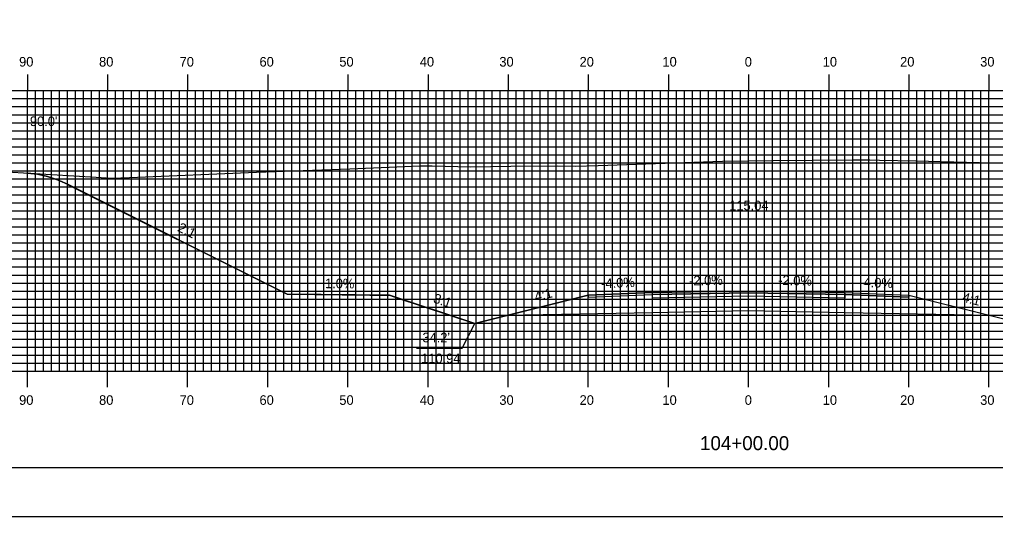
# Model space of a CAD drawing. Extents: x 1767694 to 1768037, y 442591 to 442811.
# Drawn here: x 1767768.5 to 1767890.3, y 442590.5 to 442652.5 of the extents above; entities that cross this region are included whole.
import ezdxf

# ---------------------------------------------------------------- set-up
doc = ezdxf.new("R2010")
doc.units = 0
for name, color, linetype in [('ANNOTATION', 7, 'Continuous'), ('BORDER', 7, 'Continuous'), ('D_Roadway_Centerline', 7, 'Continuous'), ('D_Roadway_Centerline_Text', 7, 'Continuous'), ('D_Roadway_Edge_Shoulder', 7, 'Continuous'), ('D_Roadway_Edge_TW', 7, 'Continuous'), ('D_Roadway_Pavement', 7, 'Continuous'), ('D_Roadway_SlopeLines', 7, 'Continuous'), ('D_Roadway_SubGrade', 7, 'Continuous'), ('D_Text_Standard', 7, 'Continuous'), ('H_V ANNOTATION', 7, 'Continuous'), ('MAJOR', 7, 'Continuous'), ('MINOR', 7, 'Continuous'), ('PLOT BOUNDARY', 7, 'Continuous'), ('S_Roadway_Centerline', 7, 'Continuous')]:
    doc.layers.add(name, color=color, linetype=linetype)

msp = doc.modelspace()

# ---------------------------------------------------------------- linework, layer by layer
at = {"layer": 'ANNOTATION'}
msp.add_lwpolyline([(1767818.02, 442611.54), (1767823.71, 442611.54), (1767825.28, 442614.6)], dxfattribs=at)
at = {"layer": 'BORDER'}
msp.add_lwpolyline([(1767709.85, 442596.67), (1768029.85, 442596.67), (1768029.85, 442806.67), (1767709.85, 442806.67)], close=True, dxfattribs=at)
at = {"layer": 'D_Roadway_Centerline'}
msp.add_lwpolyline([(1767769.45, 442633.39), (1767770.7, 442633.25), (1767771.95, 442632.96), (1767772.57, 442632.76), (1767773.2, 442632.54), (1767773.52, 442632.4), (1767774.45, 442631.99), (1767774.46, 442631.98), (1767801.88, 442618.27), (1767801.88, 442618.27), (1767812.18, 442618.17), (1767814.64, 442618.15), (1767815.56, 442617.84), (1767825.27, 442614.6), (1767825.28, 442614.6), (1767829.27, 442615.6), (1767833.59, 442616.68), (1767839.45, 442618.15), (1767839.45, 442618.15), (1767839.45, 442618.15), (1767847.45, 442618.47), (1767847.45, 442618.47), (1767849.41, 442618.51), (1767859.45, 442618.71), (1767859.46, 442618.71), (1767871.45, 442618.47), (1767871.45, 442618.47), (1767879.45, 442618.15), (1767879.45, 442618.15), (1767889.62, 442615.6), (1767893.62, 442614.6)], dxfattribs=at)
at = {"layer": 'D_Roadway_Edge_Shoulder'}
for points in [[(1767847.45, 442618.47), (1767839.45, 442618.15), (1767839.45, 442617.9), (1767847.45, 442618.22)], [(1767871.45, 442618.47), (1767879.45, 442618.15), (1767879.45, 442617.9), (1767871.45, 442618.22)]]:
    msp.add_lwpolyline(points, close=True, dxfattribs=at)
at = {"layer": 'D_Roadway_Edge_TW'}
msp.add_lwpolyline([(1767847.45, 442618.22), (1767847.45, 442618.47), (1767859.45, 442618.71), (1767871.45, 442618.47), (1767871.45, 442618.22), (1767859.45, 442618.46)], close=True, dxfattribs=at)
at = {"layer": 'D_Roadway_Pavement'}
msp.add_lwpolyline([(1767847.45, 442617.8), (1767847.45, 442618.22), (1767859.45, 442618.46), (1767871.45, 442618.22), (1767871.45, 442617.8), (1767859.45, 442618.04)], close=True, dxfattribs=at)
at = {"layer": 'D_Roadway_SlopeLines'}
for points in [[(1767814.64, 442618.15), (1767801.88, 442618.27), (1767774.45, 442631.99), (1767773.2, 442632.54), (1767771.95, 442632.96), (1767770.7, 442633.25), (1767769.45, 442633.39)], [(1767825.28, 442614.6), (1767814.64, 442618.15)], [(1767839.45, 442618.15), (1767825.28, 442614.6)], [(1767879.45, 442618.15), (1767893.62, 442614.6)]]:
    msp.add_lwpolyline(points, dxfattribs=at)
at = {"layer": 'D_Roadway_SubGrade'}
msp.add_lwpolyline([(1767847.45, 442615.97), (1767829.27, 442615.6), (1767839.45, 442618.15), (1767839.45, 442617.9), (1767847.45, 442618.22), (1767859.45, 442618.46), (1767871.45, 442618.22), (1767879.45, 442617.9), (1767879.45, 442618.15), (1767889.62, 442615.6), (1767871.45, 442615.97), (1767859.45, 442616.21)], close=True, dxfattribs=at)
at = {"layer": 'MAJOR'}
for p, q in [((1767769.45, 442645.67), (1767769.45, 442643.67)), ((1767779.45, 442645.67), (1767779.45, 442643.67)), ((1767789.45, 442645.67), (1767789.45, 442643.67)), ((1767799.45, 442645.67), (1767799.45, 442643.67)), ((1767809.45, 442645.67), (1767809.45, 442643.67)), ((1767819.45, 442645.67), (1767819.45, 442643.67)), ((1767829.45, 442645.67), (1767829.45, 442643.67)), ((1767839.45, 442645.67), (1767839.45, 442643.67)), ((1767849.45, 442645.67), (1767849.45, 442643.67)), ((1767859.45, 442645.67), (1767859.45, 442643.67)), ((1767869.45, 442645.67), (1767869.45, 442643.67)), ((1767879.45, 442645.67), (1767879.45, 442643.67)), ((1767889.45, 442645.67), (1767889.45, 442643.67)), ((1767719.45, 442643.67), (1767999.45, 442643.67)), ((1767719.45, 442643.67), (1767999.45, 442643.67)), ((1767769.45, 442608.67), (1767769.45, 442643.67)), ((1767779.45, 442608.67), (1767779.45, 442643.67)), ((1767789.45, 442608.67), (1767789.45, 442643.67)), ((1767799.45, 442608.67), (1767799.45, 442643.67)), ((1767809.45, 442608.67), (1767809.45, 442643.67)), ((1767819.45, 442608.67), (1767819.45, 442643.67)), ((1767829.45, 442608.67), (1767829.45, 442643.67)), ((1767839.45, 442608.67), (1767839.45, 442643.67)), ((1767849.45, 442608.67), (1767849.45, 442643.67)), ((1767859.45, 442608.67), (1767859.45, 442643.67)), ((1767869.45, 442608.67), (1767869.45, 442643.67)), ((1767879.45, 442608.67), (1767879.45, 442643.67)), ((1767889.45, 442608.67), (1767889.45, 442643.67)), ((1767719.45, 442638.67), (1767999.45, 442638.67)), ((1767719.45, 442633.67), (1767999.45, 442633.67)), ((1767719.45, 442628.67), (1767999.45, 442628.67)), ((1767719.45, 442623.67), (1767999.45, 442623.67)), ((1767719.45, 442618.67), (1767999.45, 442618.67)), ((1767719.45, 442613.67), (1767999.45, 442613.67)), ((1767719.45, 442608.67), (1767999.45, 442608.67)), ((1767719.45, 442608.67), (1767999.45, 442608.67)), ((1767769.45, 442606.66), (1767769.45, 442608.67)), ((1767779.45, 442606.66), (1767779.45, 442608.67)), ((1767789.45, 442606.66), (1767789.45, 442608.67)), ((1767799.45, 442606.66), (1767799.45, 442608.67)), ((1767809.45, 442606.66), (1767809.45, 442608.67)), ((1767819.45, 442606.66), (1767819.45, 442608.67)), ((1767829.45, 442606.66), (1767829.45, 442608.67)), ((1767839.45, 442606.66), (1767839.45, 442608.67)), ((1767849.45, 442606.66), (1767849.45, 442608.67)), ((1767859.45, 442606.66), (1767859.45, 442608.67)), ((1767869.45, 442606.66), (1767869.45, 442608.67)), ((1767879.45, 442606.66), (1767879.45, 442608.67)), ((1767889.45, 442606.66), (1767889.45, 442608.67))]:
    msp.add_line(p, q, dxfattribs=at)
at = {"layer": 'MINOR'}
for p, q in [((1767770.45, 442608.67), (1767770.45, 442643.67)), ((1767771.45, 442608.67), (1767771.45, 442643.67)), ((1767772.45, 442608.67), (1767772.45, 442643.67)), ((1767773.45, 442608.67), (1767773.45, 442643.67)), ((1767774.45, 442608.67), (1767774.45, 442643.67)), ((1767775.45, 442608.67), (1767775.45, 442643.67)), ((1767776.45, 442608.67), (1767776.45, 442643.67)), ((1767777.45, 442608.67), (1767777.45, 442643.67)), ((1767778.45, 442608.67), (1767778.45, 442643.67)), ((1767780.45, 442608.67), (1767780.45, 442643.67)), ((1767781.45, 442608.67), (1767781.45, 442643.67)), ((1767782.45, 442608.67), (1767782.45, 442643.67)), ((1767783.45, 442608.67), (1767783.45, 442643.67)), ((1767784.45, 442608.67), (1767784.45, 442643.67)), ((1767785.45, 442608.67), (1767785.45, 442643.67)), ((1767786.45, 442608.67), (1767786.45, 442643.67)), ((1767787.45, 442608.67), (1767787.45, 442643.67)), ((1767788.45, 442608.67), (1767788.45, 442643.67)), ((1767790.45, 442608.67), (1767790.45, 442643.67)), ((1767791.45, 442608.67), (1767791.45, 442643.67)), ((1767792.45, 442608.67), (1767792.45, 442643.67)), ((1767793.45, 442608.67), (1767793.45, 442643.67)), ((1767794.45, 442608.67), (1767794.45, 442643.67)), ((1767795.45, 442608.67), (1767795.45, 442643.67)), ((1767796.45, 442608.67), (1767796.45, 442643.67)), ((1767797.45, 442608.67), (1767797.45, 442643.67)), ((1767798.45, 442608.67), (1767798.45, 442643.67)), ((1767800.45, 442608.67), (1767800.45, 442643.67)), ((1767801.45, 442608.67), (1767801.45, 442643.67)), ((1767802.45, 442608.67), (1767802.45, 442643.67)), ((1767803.45, 442608.67), (1767803.45, 442643.67)), ((1767804.45, 442608.67), (1767804.45, 442643.67)), ((1767805.45, 442608.67), (1767805.45, 442643.67)), ((1767806.45, 442608.67), (1767806.45, 442643.67)), ((1767807.45, 442608.67), (1767807.45, 442643.67)), ((1767808.45, 442608.67), (1767808.45, 442643.67)), ((1767810.45, 442608.67), (1767810.45, 442643.67)), ((1767811.45, 442608.67), (1767811.45, 442643.67)), ((1767812.45, 442608.67), (1767812.45, 442643.67)), ((1767813.45, 442608.67), (1767813.45, 442643.67)), ((1767814.45, 442608.67), (1767814.45, 442643.67)), ((1767815.45, 442608.67), (1767815.45, 442643.67)), ((1767816.45, 442608.67), (1767816.45, 442643.67)), ((1767817.45, 442608.67), (1767817.45, 442643.67)), ((1767818.45, 442608.67), (1767818.45, 442643.67)), ((1767820.45, 442608.67), (1767820.45, 442643.67)), ((1767821.45, 442608.67), (1767821.45, 442643.67)), ((1767822.45, 442608.67), (1767822.45, 442643.67)), ((1767823.45, 442608.67), (1767823.45, 442643.67)), ((1767824.45, 442608.67), (1767824.45, 442643.67)), ((1767825.45, 442608.67), (1767825.45, 442643.67)), ((1767826.45, 442608.67), (1767826.45, 442643.67)), ((1767827.45, 442608.67), (1767827.45, 442643.67)), ((1767828.45, 442608.67), (1767828.45, 442643.67)), ((1767830.45, 442608.67), (1767830.45, 442643.67)), ((1767831.45, 442608.67), (1767831.45, 442643.67)), ((1767832.45, 442608.67), (1767832.45, 442643.67)), ((1767833.45, 442608.67), (1767833.45, 442643.67)), ((1767834.45, 442608.67), (1767834.45, 442643.67)), ((1767835.45, 442608.67), (1767835.45, 442643.67)), ((1767836.45, 442608.67), (1767836.45, 442643.67)), ((1767837.45, 442608.67), (1767837.45, 442643.67)), ((1767838.45, 442608.67), (1767838.45, 442643.67)), ((1767840.45, 442608.67), (1767840.45, 442643.67)), ((1767841.45, 442608.67), (1767841.45, 442643.67)), ((1767842.45, 442608.67), (1767842.45, 442643.67)), ((1767843.45, 442608.67), (1767843.45, 442643.67)), ((1767844.45, 442608.67), (1767844.45, 442643.67)), ((1767845.45, 442608.67), (1767845.45, 442643.67)), ((1767846.45, 442608.67), (1767846.45, 442643.67)), ((1767847.45, 442608.67), (1767847.45, 442643.67)), ((1767848.45, 442608.67), (1767848.45, 442643.67)), ((1767850.45, 442608.67), (1767850.45, 442643.67)), ((1767851.45, 442608.67), (1767851.45, 442643.67)), ((1767852.45, 442608.67), (1767852.45, 442643.67)), ((1767853.45, 442608.67), (1767853.45, 442643.67)), ((1767854.45, 442608.67), (1767854.45, 442643.67)), ((1767855.45, 442608.67), (1767855.45, 442643.67)), ((1767856.45, 442608.67), (1767856.45, 442643.67)), ((1767857.45, 442608.67), (1767857.45, 442643.67)), ((1767858.45, 442608.67), (1767858.45, 442643.67)), ((1767860.45, 442608.67), (1767860.45, 442643.67)), ((1767861.45, 442608.67), (1767861.45, 442643.67)), ((1767862.45, 442608.67), (1767862.45, 442643.67)), ((1767863.45, 442608.67), (1767863.45, 442643.67)), ((1767864.45, 442608.67), (1767864.45, 442643.67)), ((1767865.45, 442608.67), (1767865.45, 442643.67)), ((1767866.45, 442608.67), (1767866.45, 442643.67)), ((1767867.45, 442608.67), (1767867.45, 442643.67)), ((1767868.45, 442608.67), (1767868.45, 442643.67)), ((1767870.45, 442608.67), (1767870.45, 442643.67)), ((1767871.45, 442608.67), (1767871.45, 442643.67)), ((1767872.45, 442608.67), (1767872.45, 442643.67)), ((1767873.45, 442608.67), (1767873.45, 442643.67)), ((1767874.45, 442608.67), (1767874.45, 442643.67)), ((1767875.45, 442608.67), (1767875.45, 442643.67)), ((1767876.45, 442608.67), (1767876.45, 442643.67)), ((1767877.45, 442608.67), (1767877.45, 442643.67)), ((1767878.45, 442608.67), (1767878.45, 442643.67)), ((1767880.45, 442608.67), (1767880.45, 442643.67)), ((1767881.45, 442608.67), (1767881.45, 442643.67)), ((1767882.45, 442608.67), (1767882.45, 442643.67)), ((1767883.45, 442608.67), (1767883.45, 442643.67)), ((1767884.45, 442608.67), (1767884.45, 442643.67)), ((1767885.45, 442608.67), (1767885.45, 442643.67)), ((1767886.45, 442608.67), (1767886.45, 442643.67)), ((1767887.45, 442608.67), (1767887.45, 442643.67)), ((1767888.45, 442608.67), (1767888.45, 442643.67)), ((1767719.45, 442642.67), (1767999.45, 442642.67)), ((1767719.45, 442641.67), (1767999.45, 442641.67)), ((1767719.45, 442640.67), (1767999.45, 442640.67)), ((1767719.45, 442639.67), (1767999.45, 442639.67)), ((1767719.45, 442637.67), (1767999.45, 442637.67)), ((1767719.45, 442636.67), (1767999.45, 442636.67)), ((1767719.45, 442635.67), (1767999.45, 442635.67)), ((1767719.45, 442634.67), (1767999.45, 442634.67)), ((1767719.45, 442632.67), (1767999.45, 442632.67)), ((1767719.45, 442631.67), (1767999.45, 442631.67)), ((1767719.45, 442630.67), (1767999.45, 442630.67)), ((1767719.45, 442629.67), (1767999.45, 442629.67)), ((1767719.45, 442627.67), (1767999.45, 442627.67)), ((1767719.45, 442626.67), (1767999.45, 442626.67)), ((1767719.45, 442625.67), (1767999.45, 442625.67)), ((1767719.45, 442624.67), (1767999.45, 442624.67)), ((1767719.45, 442622.67), (1767999.45, 442622.67)), ((1767719.45, 442621.67), (1767999.45, 442621.67)), ((1767719.45, 442620.67), (1767999.45, 442620.67)), ((1767719.45, 442619.67), (1767999.45, 442619.67)), ((1767719.45, 442617.67), (1767999.45, 442617.67)), ((1767719.45, 442616.67), (1767999.45, 442616.67)), ((1767719.45, 442615.67), (1767999.45, 442615.67)), ((1767719.45, 442614.67), (1767999.45, 442614.67)), ((1767719.45, 442612.67), (1767999.45, 442612.67)), ((1767719.45, 442611.67), (1767999.45, 442611.67)), ((1767719.45, 442610.67), (1767999.45, 442610.67)), ((1767719.45, 442609.67), (1767999.45, 442609.67))]:
    msp.add_line(p, q, dxfattribs=at)
at = {"layer": 'PLOT BOUNDARY'}
msp.add_lwpolyline([(1767693.66, 442590.55), (1768033.66, 442590.55), (1768033.66, 442810.55), (1767693.66, 442810.55)], close=True, dxfattribs=at)
at = {"layer": 'S_Roadway_Centerline'}
msp.add_lwpolyline([(1767766.88, 442633.56), (1767778.05, 442632.86), (1767779.3, 442632.8), (1767780.01, 442632.74), (1767782.21, 442632.82), (1767798.04, 442633.49), (1767809.7, 442633.93), (1767818.51, 442634.28), (1767819.95, 442634.3), (1767824.79, 442634.18), (1767829.77, 442634.24), (1767835.65, 442634.28), (1767837.81, 442634.25), (1767840.68, 442634.31), (1767856.2, 442634.86), (1767862.5, 442634.96), (1767872.47, 442635.02), (1767874.57, 442635.03), (1767875.77, 442635.01), (1767880.33, 442634.9), (1767894.58, 442634.55)], dxfattribs=at)

# ---------------------------------------------------------------- texts
at = {"layer": 'ANNOTATION'}
for s, rotation, p in [('2:1', 333.435, (1767788.1, 442626.2)), ('-4.0%', 2.2905, (1767841.08, 442619.01)), ('-2.0%', 1.1458, (1767852.04, 442619.36)), ('-2.0%', 358.8542, (1767863.14, 442619.43)), ('-4.0%', 357.7095, (1767873.24, 442619.2)), ('1.0%', 359.4301, (1767806.59, 442619.03)), ('3:1', 341.5622, (1767820.02, 442617.26)), ('4:1', 14.0377, (1767832.9, 442617.37)), ('4:1', 345.9611, (1767886.04, 442617.36))]:
    msp.add_text(s, height=1.2, rotation=rotation, dxfattribs=at).set_placement(p)
for s, p in [("34.2'", (1767818.75, 442612.27)), ('110.94', (1767818.59, 442609.67))]:
    msp.add_text(s, height=1.2, dxfattribs=at).set_placement(p)
at = {"layer": 'D_Roadway_Centerline'}
for s, p in [('C', (1767859.44, 442618.71)), ('L', (1767859.45, 442618.7))]:
    msp.add_text(s, height=0.0146, dxfattribs=at).set_placement(p)
at = {"layer": 'D_Roadway_Centerline_Text'}
msp.add_text('115.04', height=1.2, dxfattribs=at).set_placement((1767857.03, 442628.74))
at = {"layer": 'D_Text_Standard'}
msp.add_text("90.0'", height=1.2, dxfattribs=at).set_placement((1767769.77, 442639.25))
at = {"layer": 'H_V ANNOTATION'}
for s, height, p in [('90', 1.2, (1767768.42, 442646.67)), ('80', 1.2, (1767778.4, 442646.67)), ('70', 1.2, (1767788.45, 442646.67)), ('60', 1.2, (1767798.42, 442646.67)), ('50', 1.2, (1767808.38, 442646.67)), ('40', 1.2, (1767818.42, 442646.67)), ('30', 1.2, (1767828.35, 442646.67)), ('20', 1.2, (1767838.36, 442646.67)), ('10', 1.2, (1767848.7, 442646.67)), ('0', 1.2, (1767858.97, 442646.67)), ('10', 1.2, (1767868.7, 442646.67)), ('20', 1.2, (1767878.36, 442646.67)), ('30', 1.2, (1767888.35, 442646.67)), ('90', 1.2, (1767768.42, 442604.47)), ('80', 1.2, (1767778.4, 442604.47)), ('70', 1.2, (1767788.45, 442604.47)), ('60', 1.2, (1767798.42, 442604.47)), ('50', 1.2, (1767808.38, 442604.47)), ('40', 1.2, (1767818.42, 442604.47)), ('30', 1.2, (1767828.35, 442604.47)), ('20', 1.2, (1767838.36, 442604.47)), ('10', 1.2, (1767848.7, 442604.47)), ('0', 1.2, (1767858.97, 442604.47)), ('10', 1.2, (1767868.7, 442604.47)), ('20', 1.2, (1767878.36, 442604.47)), ('30', 1.2, (1767888.35, 442604.47)), ('104+00.00', 1.75, (1767853.39, 442598.82))]:
    msp.add_text(s, height=height, dxfattribs=at).set_placement(p)

doc.saveas('drawing.dxf')
